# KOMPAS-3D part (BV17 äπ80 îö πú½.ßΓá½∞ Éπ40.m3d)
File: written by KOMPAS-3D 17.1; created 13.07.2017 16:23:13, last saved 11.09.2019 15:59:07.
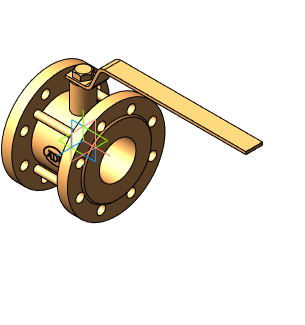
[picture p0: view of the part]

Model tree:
1. Операция без истории:3  (labels: Сталь 20  ГОСТ 1050-88)

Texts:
  DISO1
  DISO2
  BV17 Ду10 ФФ Ру40 угл. сталь
  BV17 Ду15 ФФ Ру40 угл. сталь
  BV17 Ду20 ФФ Ру40 угл. сталь
  BV17 Ду25 ФФ Ру40 угл. сталь
  BV17 Ду32 ФФ Ру40 угл. сталь
  BV17 Ду40 ФФ Ру40 угл. сталь
  BV17 Ду50 ФФ Ру40 угл. сталь
  BV17 Ду65 ФФ Ру40 угл. сталь
  BV17 Ду80 ФФ Ру40 угл. сталь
